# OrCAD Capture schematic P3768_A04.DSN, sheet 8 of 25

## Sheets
8 0017_DISPLAYPORT_HDMI: size Custom
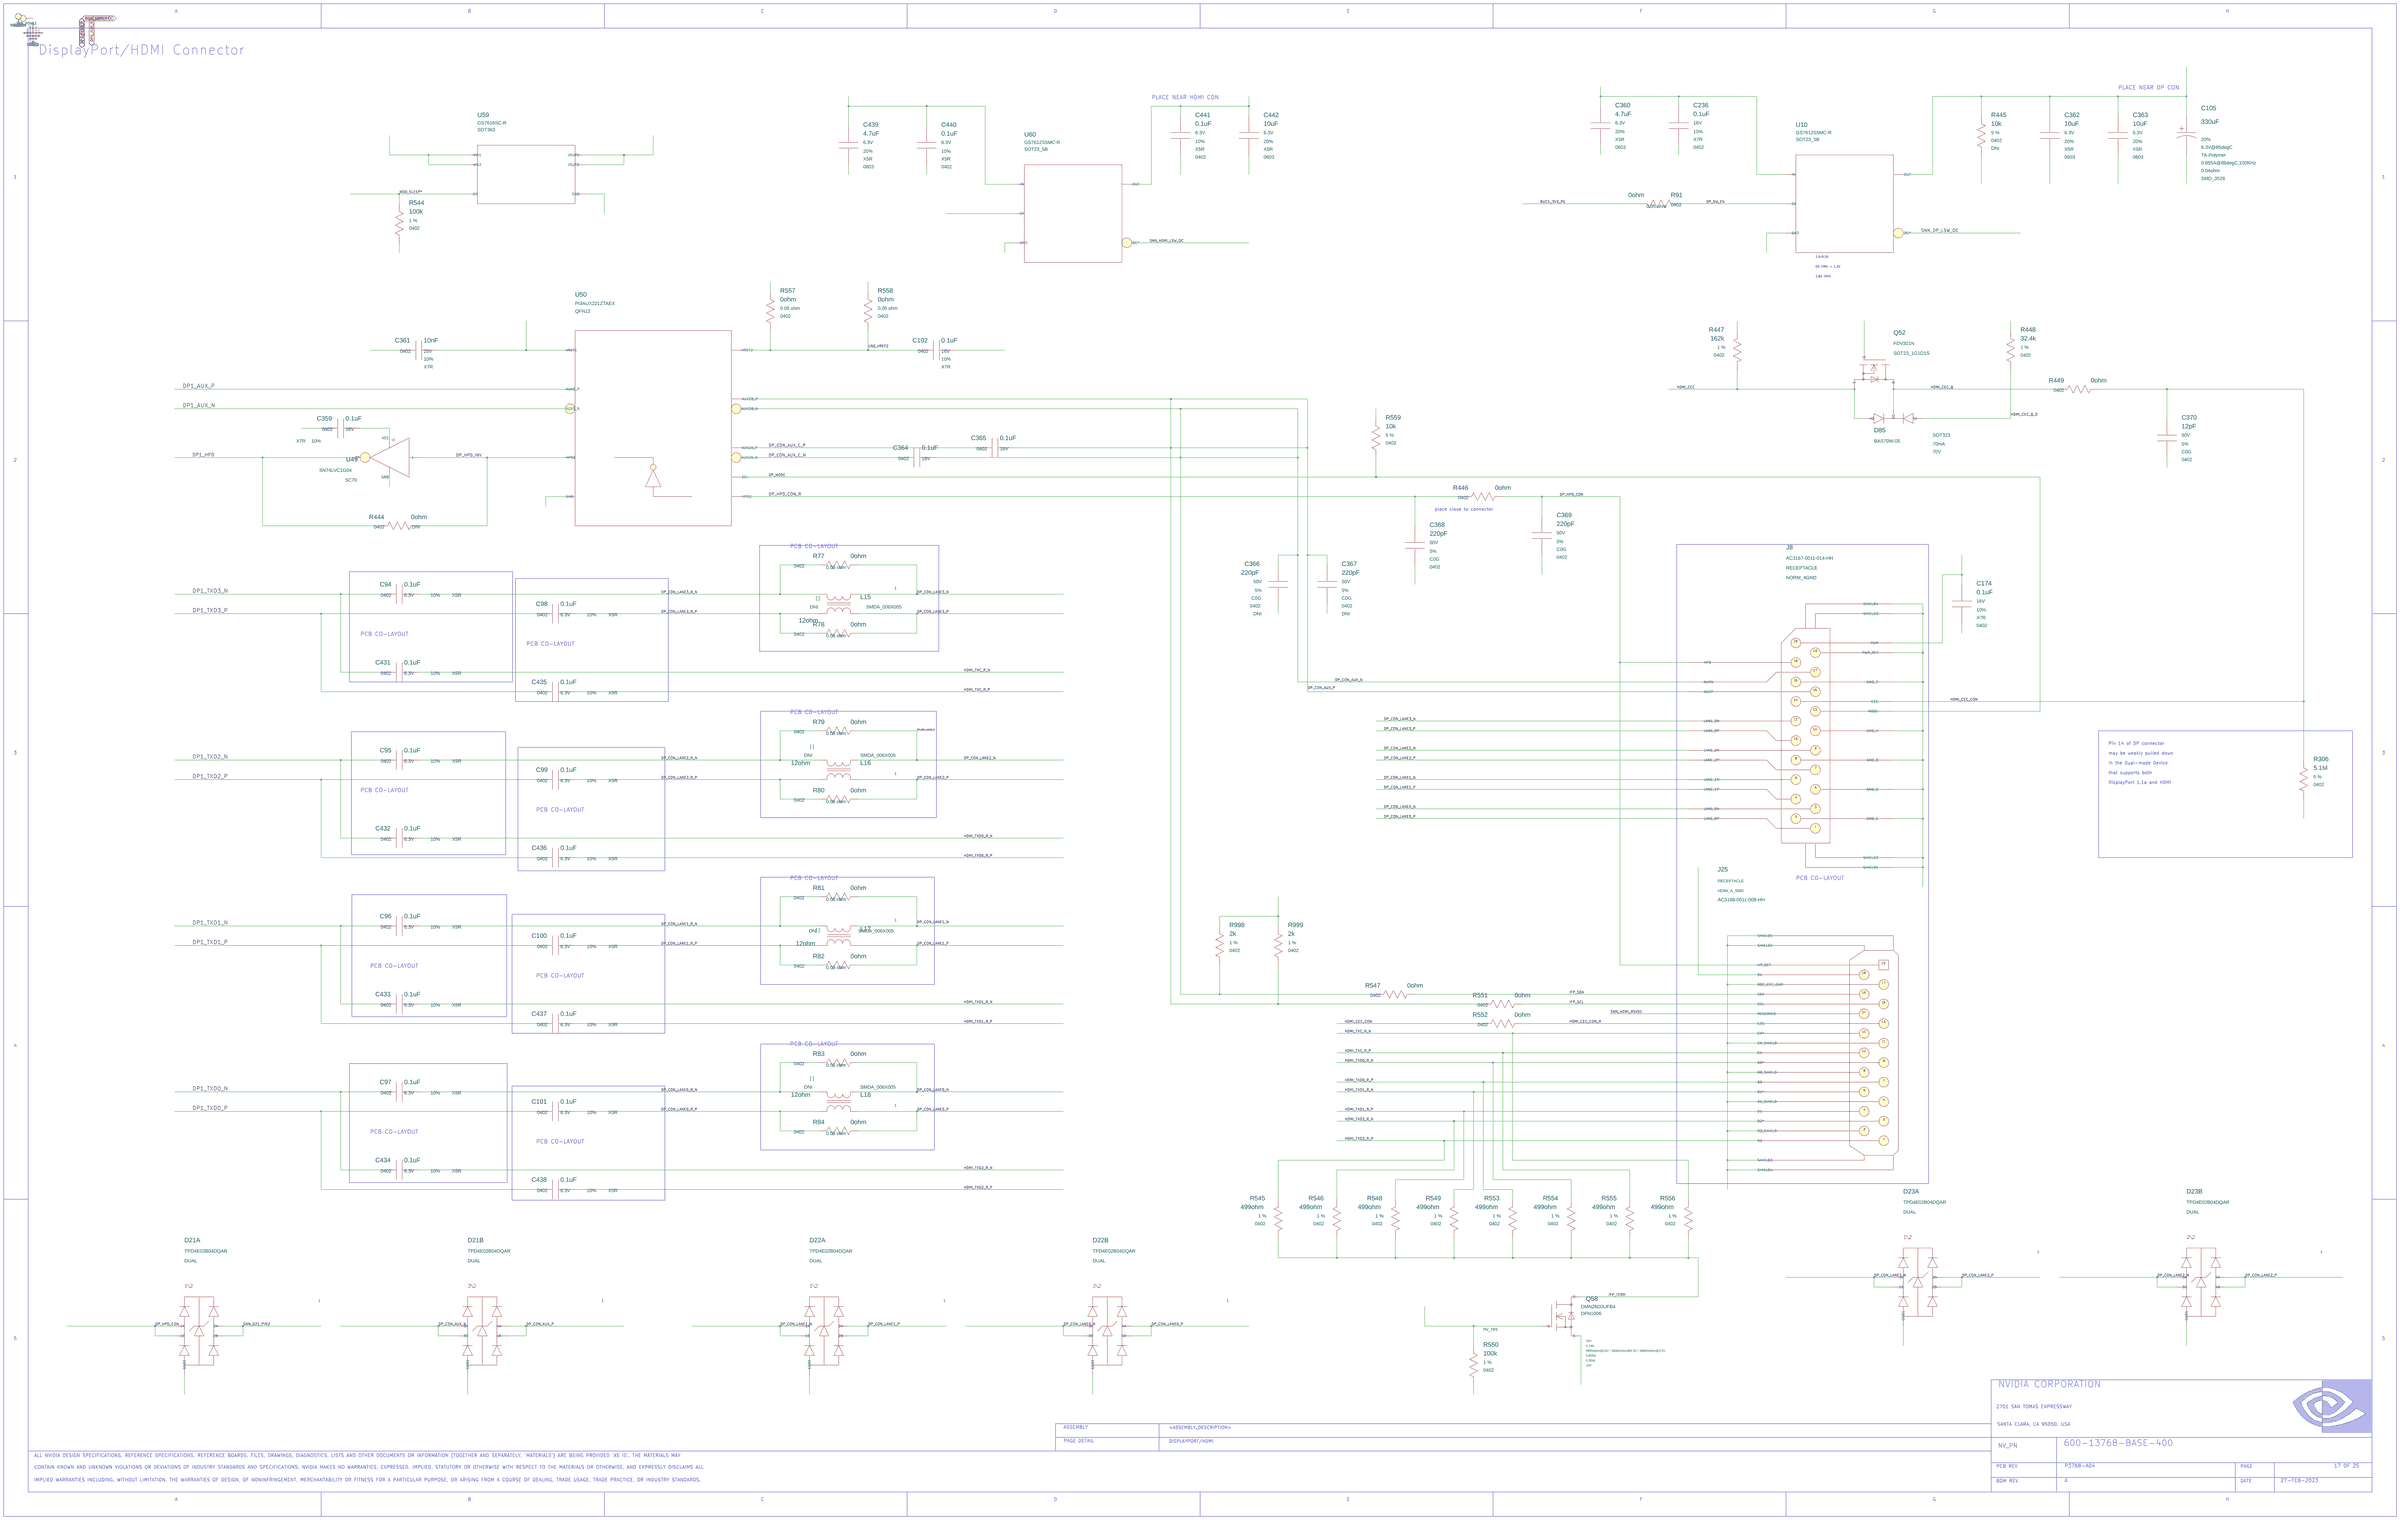
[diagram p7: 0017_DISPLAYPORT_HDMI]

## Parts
C94  0.1uF  [0402]
C95  0.1uF  [0402]
C96  0.1uF  [0402]
C97  0.1uF  [0402]
C98  0.1uF  [0402]
C99  0.1uF  [0402]
C100  0.1uF  [0402]
C101  0.1uF  [0402]
C102  0.1uF  [0402]
C105  330uF  [CAP_SMD_3528]
C174  0.1uF  [0402]
C236  0.1uF  [0402]
C359  0.1uF  [0402]
C360  4.7uF  [0603]
C361  10nF  [0402]
C362  10uF  [0603]
C363  10uF  [0603]
C364  0.1uF  [0402]
C365  0.1uF  [0402]
C366  220pF  [0402]
C367  220pF  [0402]
C368  220pF  [0402]
C369  220pF  [0402]
C370  12pF  [0402]
C431  0.1uF  [0402]
C432  0.1uF  [0402]
C433  0.1uF  [0402]
C434  0.1uF  [0402]
C435  0.1uF  [0402]
C436  0.1uF  [0402]
C437  0.1uF  [0402]
C438  0.1uF  [0402]
C439  4.7uF  [0603]
C440  0.1uF  [0402]
C441  0.1uF  [0402]
C442  10uF  [0603]
D21  D_ESD_DIFFPAIR  [TSLP10_P050_025X010]  (sections A,B)
D22  D_ESD_DIFFPAIR  [TSLP10_P050_025X010]  (sections A,B)
D23  D_ESD_DIFFPAIR  [TSLP10_P050_025X010]  (sections A,B)
D85  D_3PIN_CC  [SOT323]
J8  CON_DISPLAYPORT  [CON_DP_020_SMT_RA_F_P050]
J25  CON_HDMI  [CON_HDMI_019_SMT_RA_F_P005_R]
L15  12ohm  [FILTER_004_SMD_006X005]
L16  12ohm  [FILTER_004_SMD_006X005]
L17  12ohm  [FILTER_004_SMD_006X005]
L18  12ohm  [FILTER_004_SMD_006X005]
Q52  Q_FET_N_ENH  [SOT23]
Q58  Q_FET_N_ENH  [DFET_003_SMD_010X006_B]
R77  0ohm  [0402]
R78  0ohm  [0402]
R79  0ohm  [0402]
R80  0ohm  [0402]
R81  0ohm  [0402]
R82  0ohm  [0402]
R83  0ohm  [0402]
R84  0ohm  [0402]
R91  0ohm  [0402]
R306  5.1M  [0402]
R444  0ohm  [0402]
R445  10k  [0402]
R446  0ohm  [0402]
R447  162k  [0402]
R448  32.4k  [0402]
R449  0ohm  [0402]
R544  100k  [0402]
R545  499ohm  [0402]
R546  499ohm  [0402]
R547  0ohm  [0402]
R548  499ohm  [0402]
R549  499ohm  [0402]
R550  100k  [0402]
R551  0ohm  [0402]
R552  0ohm  [0402]
R553  499ohm  [0402]
R554  499ohm  [0402]
R555  499ohm  [0402]
R556  499ohm  [0402]
R557  0ohm  [0402]
R558  0ohm  [0402]
R559  10k  [0402]
R998  2k  [0402]
R999  2k  [0402]
U10  U_POWER_SW  [SOT23_5]
U49  U_NOT  [SC70_5]
U50  U_AUX_DDC_INTERFACE  [QFN012Q_P040_0020_B]
U59  U_SW_LOAD  [SC70_6]
U60  U_POWER_SW  [SOT23_5]

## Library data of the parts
C94 = C: ASSEMBLY: DISPLAYPORT; CDS_LIB: discrete; CDS_PART_NAME: C_0402-0.1UF,X5R,10%,6.3V,039-0007-000; CDS_PHYS_PART_NAME: C_0402-0.1UF,X5R,10%,6.3V,039-0007-000-0.1UF,039-0007-000; CDS_SEC: 1; DEVICE_TYPENAME: C_0402-01UFX5R1063V039-0007-000-01UF039-0007-000; DRAWING: @P3768_A04_LIB.P3768_A04(SCH_1):PAGE17; MAT: X5R; MAX_VOLTAGE: 6.3V; NO_XNET: 1; NV_PN: 039-0007-000; PATH: I276; PHYS_PAGE: 17; PSPICETEMPLATE: X^@REFDES  %1    %2   @NV_PN; ROT: 0; SEC: 1; SIGNAL_MODEL: nv_cap; TOL: 10%; VER: 2; XY: (-10100,4600)
C95 = C: ASSEMBLY: DISPLAYPORT; CDS_LIB: discrete; CDS_PART_NAME: C_0402-0.1UF,X5R,10%,6.3V,039-0007-000; CDS_PHYS_PART_NAME: C_0402-0.1UF,X5R,10%,6.3V,039-0007-000-0.1UF,039-0007-000; CDS_SEC: 1; DEVICE_TYPENAME: C_0402-01UFX5R1063V039-0007-000-01UF039-0007-000; DRAWING: @P3768_A04_LIB.P3768_A04(SCH_1):PAGE17; MAT: X5R; MAX_VOLTAGE: 6.3V; NO_XNET: 1; NV_PN: 039-0007-000; PATH: I273; PHYS_PAGE: 17; PSPICETEMPLATE: X^@REFDES  %1    %2   @NV_PN; ROT: 0; SEC: 1; SIGNAL_MODEL: nv_cap; TOL: 10%; VER: 2; XY: (-10100,3750)
C96 = C: ASSEMBLY: DISPLAYPORT; CDS_LIB: discrete; CDS_PART_NAME: C_0402-0.1UF,X5R,10%,6.3V,039-0007-000; CDS_PHYS_PART_NAME: C_0402-0.1UF,X5R,10%,6.3V,039-0007-000-0.1UF,039-0007-000; CDS_SEC: 1; DEVICE_TYPENAME: C_0402-01UFX5R1063V039-0007-000-01UF039-0007-000; DRAWING: @P3768_A04_LIB.P3768_A04(SCH_1):PAGE17; MAT: X5R; MAX_VOLTAGE: 6.3V; NO_XNET: 1; NV_PN: 039-0007-000; PATH: I272; PHYS_PAGE: 17; PSPICETEMPLATE: X^@REFDES  %1    %2   @NV_PN; ROT: 0; SEC: 1; SIGNAL_MODEL: nv_cap; TOL: 10%; VER: 2; XY: (-10100,2900)
C97 = C: ASSEMBLY: DISPLAYPORT; CDS_LIB: discrete; CDS_PART_NAME: C_0402-0.1UF,X5R,10%,6.3V,039-0007-000; CDS_PHYS_PART_NAME: C_0402-0.1UF,X5R,10%,6.3V,039-0007-000-0.1UF,039-0007-000; CDS_SEC: 1; DEVICE_TYPENAME: C_0402-01UFX5R1063V039-0007-000-01UF039-0007-000; DRAWING: @P3768_A04_LIB.P3768_A04(SCH_1):PAGE17; MAT: X5R; MAX_VOLTAGE: 6.3V; NO_XNET: 1; NV_PN: 039-0007-000; PATH: I271; PHYS_PAGE: 17; PSPICETEMPLATE: X^@REFDES  %1    %2   @NV_PN; ROT: 0; SEC: 1; SIGNAL_MODEL: nv_cap; TOL: 10%; VER: 2; XY: (-10100,2050)
C98 = C: ASSEMBLY: DISPLAYPORT; CDS_LIB: discrete; CDS_PART_NAME: C_0402-0.1UF,X5R,10%,6.3V,039-0007-000; CDS_PHYS_PART_NAME: C_0402-0.1UF,X5R,10%,6.3V,039-0007-000-0.1UF,039-0007-000; CDS_SEC: 1; DEVICE_TYPENAME: C_0402-01UFX5R1063V039-0007-000-01UF039-0007-000; DRAWING: @P3768_A04_LIB.P3768_A04(SCH_1):PAGE17; MAT: X5R; MAX_VOLTAGE: 6.3V; NO_XNET: 1; NV_PN: 039-0007-000; PATH: I288; PHYS_PAGE: 17; PSPICETEMPLATE: X^@REFDES  %1    %2   @NV_PN; ROT: 0; SEC: 1; SIGNAL_MODEL: nv_cap; TOL: 10%; VER: 2; XY: (-9300,4500)
C99 = C: ASSEMBLY: DISPLAYPORT; CDS_LIB: discrete; CDS_PART_NAME: C_0402-0.1UF,X5R,10%,6.3V,039-0007-000; CDS_PHYS_PART_NAME: C_0402-0.1UF,X5R,10%,6.3V,039-0007-000-0.1UF,039-0007-000; CDS_SEC: 1; DEVICE_TYPENAME: C_0402-01UFX5R1063V039-0007-000-01UF039-0007-000; DRAWING: @P3768_A04_LIB.P3768_A04(SCH_1):PAGE17; MAT: X5R; MAX_VOLTAGE: 6.3V; NO_XNET: 1; NV_PN: 039-0007-000; PATH: I279; PHYS_PAGE: 17; PSPICETEMPLATE: X^@REFDES  %1    %2   @NV_PN; ROT: 0; SEC: 1; SIGNAL_MODEL: nv_cap; TOL: 10%; VER: 2; XY: (-9300,3650)
C100 = C: ASSEMBLY: DISPLAYPORT; CDS_LIB: discrete; CDS_PART_NAME: C_0402-0.1UF,X5R,10%,6.3V,039-0007-000; CDS_PHYS_PART_NAME: C_0402-0.1UF,X5R,10%,6.3V,039-0007-000-0.1UF,039-0007-000; CDS_SEC: 1; DEVICE_TYPENAME: C_0402-01UFX5R1063V039-0007-000-01UF039-0007-000; DRAWING: @P3768_A04_LIB.P3768_A04(SCH_1):PAGE17; MAT: X5R; MAX_VOLTAGE: 6.3V; NO_XNET: 1; NV_PN: 039-0007-000; PATH: I278; PHYS_PAGE: 17; PSPICETEMPLATE: X^@REFDES  %1    %2   @NV_PN; ROT: 0; SEC: 1; SIGNAL_MODEL: nv_cap; TOL: 10%; VER: 2; XY: (-9300,2800)
C101 = C: ASSEMBLY: DISPLAYPORT; CDS_LIB: discrete; CDS_PART_NAME: C_0402-0.1UF,X5R,10%,6.3V,039-0007-000; CDS_PHYS_PART_NAME: C_0402-0.1UF,X5R,10%,6.3V,039-0007-000-0.1UF,039-0007-000; CDS_SEC: 1; DEVICE_TYPENAME: C_0402-01UFX5R1063V039-0007-000-01UF039-0007-000; DRAWING: @P3768_A04_LIB.P3768_A04(SCH_1):PAGE17; MAT: X5R; MAX_VOLTAGE: 6.3V; NO_XNET: 1; NV_PN: 039-0007-000; PATH: I277; PHYS_PAGE: 17; PSPICETEMPLATE: X^@REFDES  %1    %2   @NV_PN; ROT: 0; SEC: 1; SIGNAL_MODEL: nv_cap; TOL: 10%; VER: 2; XY: (-9300,1950)
C102 = C: ASSEMBLY: DP_AND_HDMI; CDS_LIB: discrete; CDS_PART_NAME: C_0402-0.1UF,X7R,10%,16V,032-0793-000; CDS_PHYS_PART_NAME: C_0402-0.1UF,X7R,10%,16V,032-0793-000-0.1UF,032-0793-000; CDS_SEC: 1; DEVICE_TYPENAME: C_0402-01UFX7R1016V032-0793-000-01UF032-0793-000; DRAWING: @P3768_A04_LIB.P3768_A04(SCH_1):PAGE17; MAT: X7R; MAX_VOLTAGE: 16V; NV_PN: 032-0793-000; PATH: I129; PHYS_PAGE: 17; PSPICETEMPLATE: X^@REFDES  %1    %2   @NV_PN; ROT: 0; SEC: 1; SIGNAL_MODEL: nv_cap; TOL: 10%; VER: 2; XY: (-7350,5850)
C105 = C_POL: ASSEMBLY: DISPLAYPORT; CDS_LIB: discrete; CDS_PART_NAME: C_POL_SMD_3528-330UF,TA-POLYMER,20%,6.3V@85DEGC,0.04OHM,9.999UH,0.855A@85DEGC,100KHZ,032-0696-000; CDS_PHYS_PART_NAME: C_POL_SMD_3528-330UF,TA-POLYMER,20%,6.3V@85DEGC,0.04OHM,9.999UH,0.855A@85DEGC,100KHZ,032-0696-000-032-0696-000,330UF; CDS_SEC: 1; DEVICE_TYPENAME: C_POL_SMD_3528-330UFTA-POLYMER2063V85DEGC004OHM9999UH0855A85DEGC100KHZ032-0696-000-032-0696-000330UF; DRAWING: @P3768_A04_LIB.P3768_A04(SCH_1):PAGE17; ESL: 9.999uH; ESR: 0.04ohm; MAT: TA-Polymer; MAX_VOLTAGE: 6.3V@85degC; NV_PN: 032-0696-000; PACK_TYPE: SMD_3528; PATH: I212; PHYS_PAGE: 17; PSPICETEMPLATE: X^@REFDES  %1    %2   @NV_PN; RIPPLE_CURRENT: 0.855A@85degC,100KHz; ROT: 0; SEC: 1; SIGNAL_MODEL: nv_capp; TOL: 20%; VER: 1; XY: (-950,6950)
C174 = C#1: ASSEMBLY: DISPLAYPORT; CDS_LIB: discrete; CDS_PART_NAME: C_0402-0.1UF,X7R,10%,16V,032-0793-000; CDS_PHYS_PART_NAME: C_0402-0.1UF,X7R,10%,16V,032-0793-000-0.1UF,032-0793-000; CDS_SEC: 1; CHIPS_PART_NAME: C; DEVICE_TYPENAME: C_0402-01UFX7R1016V032-0793-000-01UF032-0793-000; DRAWING: @P3768_A04_LIB.P3768_A04(SCH_1):PAGE17; MAT: X7R; MAX_VOLTAGE: 16V; NV_PN: 032-0793-000; PATH: I215; PHYS_PAGE: 17; PSPICETEMPLATE: X^@REFDES  %1    %2   @NV_PN; ROT: 0; SEC: 1; SIGNAL_MODEL: nv_cap; TOL: 10%; VER: 1; XY: (-2100,4550)
C236 = C#1: ASSEMBLY: DISPLAYPORT; CDS_LIB: discrete; CDS_PART_NAME: C_0402-0.1UF,X7R,10%,16V,032-0793-000; CDS_PHYS_PART_NAME: C_0402-0.1UF,X7R,10%,16V,032-0793-000-0.1UF,032-0793-000; CDS_SEC: 1; CHIPS_PART_NAME: C; DEVICE_TYPENAME: C_0402-01UFX7R1016V032-0793-000-01UF032-0793-000; DRAWING: @P3768_A04_LIB.P3768_A04(SCH_1):PAGE17; ESL: N/A; ESR: N/A; MAT: X7R; MAX_VOLTAGE: 16V; NV_PN: 032-0793-000; PATH: I197; PHYS_PAGE: 17; PSPICETEMPLATE: X^@REFDES  %1    %2   @NV_PN; ROT: 0; SEC: 1; SIGNAL_MODEL: nv_cap; TOL: 10%; VER: 1; XY: (-3550,7000)
C359 = C: ASSEMBLY: DP_AND_HDMI; CDS_LIB: discrete; CDS_PART_NAME: C_0402-0.1UF,X7R,10%,16V,032-0793-000; CDS_PHYS_PART_NAME: C_0402-0.1UF,X7R,10%,16V,032-0793-000-0.1UF,032-0793-000; CDS_SEC: 1; DEVICE_TYPENAME: C_0402-01UFX7R1016V032-0793-000-01UF032-0793-000; DRAWING: @P3768_A04_LIB.P3768_A04(SCH_1):PAGE17; MAT: X7R; MAX_VOLTAGE: 16V; NV_PN: 032-0793-000; PATH: I296; PHYS_PAGE: 17; ROT: 0; SEC: 1; SIGNAL_MODEL: nv_cap; TOL: 10%; VER: 2; XY: (-10400,5450)
C360 = C#1: ASSEMBLY: DISPLAYPORT; CDS_LIB: discrete; CDS_PART_NAME: C_0603-4.7UF,X5R,20%,6.3V,032-2124-000; CDS_PHYS_PART_NAME: C_0603-4.7UF,X5R,20%,6.3V,032-2124-000-032-2124-000,4.7UF; CDS_SEC: 1; CHIPS_PART_NAME: C; DEVICE_TYPENAME: C_0603-47UFX5R2063V032-2124-000-032-2124-00047UF; DRAWING: @P3768_A04_LIB.P3768_A04(SCH_1):PAGE17; MAT: X5R; MAX_VOLTAGE: 6.3V; NV_PN: 032-2124-000; PATH: I218; PHYS_PAGE: 17; PSPICETEMPLATE: X^@REFDES  %1    %2   @NV_PN; ROT: 0; SEC: 1; SIGNAL_MODEL: nv_cap; TOL: 20%; VER: 1; XY: (-3950,7000)
C361 = C: ASSEMBLY: DP_AND_HDMI; CDS_LIB: discrete; CDS_PART_NAME: C_0402-10NF,X7R,10%,25V,036-0019-000; CDS_PHYS_PART_NAME: C_0402-10NF,X7R,10%,25V,036-0019-000-036-0019-000,10NF; CDS_SEC: 1; DEVICE_TYPENAME: C_0402-10NFX7R1025V036-0019-000-036-0019-00010NF; DRAWING: @P3768_A04_LIB.P3768_A04(SCH_1):PAGE17; MAT: X7R; MAX_VOLTAGE: 25V; NV_PN: 036-0019-000; PATH: I176; PHYS_PAGE: 17; PSPICETEMPLATE: X^@REFDES  %1    %2   @NV_PN; ROT: 0; SEC: 1; SIGNAL_MODEL: nv_cap; TOL: 10%; VER: 2; XY: (-10000,5850)
C362 = C#1: ASSEMBLY: DISPLAYPORT; CDS_LIB: discrete; CDS_PART_NAME: C_0603-10UF,X5R,20%,6.3V,032-2136-000; CDS_PHYS_PART_NAME: C_0603-10UF,X5R,20%,6.3V,032-2136-000-032-2136-000,10UF; CDS_SEC: 1; CHIPS_PART_NAME: C; DEVICE_TYPENAME: C_0603-10UFX5R2063V032-2136-000-032-2136-00010UF; DRAWING: @P3768_A04_LIB.P3768_A04(SCH_1):PAGE17; MAT: X5R; MAX_VOLTAGE: 6.3V; NV_PN: 032-2136-000; PATH: I220; PHYS_PAGE: 17; PSPICETEMPLATE: X^@REFDES  %1    %2   @NV_PN; ROT: 0; SEC: 1; SIGNAL_MODEL: nv_cap; TOL: 20%; VER: 1; XY: (-1650,6950)
C363 = C#1: ASSEMBLY: DISPLAYPORT; CDS_LIB: discrete; CDS_PART_NAME: C_0603-10UF,X5R,20%,6.3V,032-2136-000; CDS_PHYS_PART_NAME: C_0603-10UF,X5R,20%,6.3V,032-2136-000-032-2136-000,10UF; CDS_SEC: 1; CHIPS_PART_NAME: C; DEVICE_TYPENAME: C_0603-10UFX5R2063V032-2136-000-032-2136-00010UF; DRAWING: @P3768_A04_LIB.P3768_A04(SCH_1):PAGE17; MAT: X5R; MAX_VOLTAGE: 6.3V; NV_PN: 032-2136-000; PATH: I219; PHYS_PAGE: 17; PSPICETEMPLATE: X^@REFDES  %1    %2   @NV_PN; ROT: 0; SEC: 1; SIGNAL_MODEL: nv_cap; TOL: 20%; VER: 1; XY: (-1300,6950)
C364 = C: ASSEMBLY: DP_AND_HDMI; CDS_LIB: discrete; CDS_PART_NAME: C_0402-0.1UF,X7R,10%,16V,032-0793-000; CDS_PHYS_PART_NAME: C_0402-0.1UF,X7R,10%,16V,032-0793-000-0.1UF,032-0793-000; CDS_SEC: 1; DEVICE_TYPENAME: C_0402-01UFX7R1016V032-0793-000-01UF032-0793-000; DRAWING: @P3768_A04_LIB.P3768_A04(SCH_1):PAGE17; MAT: X7R; MAX_VOLTAGE: 16V; NV_PN: 032-0793-000; PATH: I142; PHYS_PAGE: 17; PSPICETEMPLATE: X^@REFDES  %1    %2   @NV_PN; ROT: 0; SEC: 1; SIGNAL_MODEL: nv_cap; TOL: 10%; VER: 2; XY: (-7450,5300)
C365 = C: ASSEMBLY: DP_AND_HDMI; CDS_LIB: discrete; CDS_PART_NAME: C_0402-0.1UF,X7R,10%,16V,032-0793-000; CDS_PHYS_PART_NAME: C_0402-0.1UF,X7R,10%,16V,032-0793-000-0.1UF,032-0793-000; CDS_SEC: 1; DEVICE_TYPENAME: C_0402-01UFX7R1016V032-0793-000-01UF032-0793-000; DRAWING: @P3768_A04_LIB.P3768_A04(SCH_1):PAGE17; MAT: X7R; MAX_VOLTAGE: 16V; NV_PN: 032-0793-000; PATH: I141; PHYS_PAGE: 17; PSPICETEMPLATE: X^@REFDES  %1    %2   @NV_PN; ROT: 0; SEC: 1; SIGNAL_MODEL: nv_cap; TOL: 10%; VER: 2; XY: (-7050,5350)
C366 = C#1: ASSEMBLY: DISPLAYPORT; CDS_LIB: discrete; CDS_PART_NAME: C_0402-220PF,C0G,5%,50V,035-0024-000; CDS_PHYS_PART_NAME: C_0402-220PF,C0G,5%,50V,035-0024-000-035-0024-000,220PF; CDS_SEC: 1; CHIPS_PART_NAME: C; DEVICE_TYPENAME: C_0402-220PFC0G550V035-0024-000-035-0024-000220PF; DRAWING: @P3768_A04_LIB.P3768_A04(SCH_1):PAGE17; MAT: C0G; MAX_VOLTAGE: 50V; NV_PN: 035-0024-000; PATH: I143; PHYS_PAGE: 17; PSPICETEMPLATE: X^@REFDES  %1    %2   @NV_PN; ROT: 2; SEC: 1; SIGNAL_MODEL: nv_cap; SKU: DNI; TOL: 5%; VER: 1; XY: (-5600,4650)
C367 = C#1: ASSEMBLY: DISPLAYPORT; CDS_LIB: discrete; CDS_PART_NAME: C_0402-220PF,C0G,5%,50V,035-0024-000; CDS_PHYS_PART_NAME: C_0402-220PF,C0G,5%,50V,035-0024-000-035-0024-000,220PF; CDS_SEC: 1; CHIPS_PART_NAME: C; DEVICE_TYPENAME: C_0402-220PFC0G550V035-0024-000-035-0024-000220PF; DRAWING: @P3768_A04_LIB.P3768_A04(SCH_1):PAGE17; MAT: C0G; MAX_VOLTAGE: 50V; NV_PN: 035-0024-000; PATH: I144; PHYS_PAGE: 17; PSPICETEMPLATE: X^@REFDES  %1    %2   @NV_PN; ROT: 0; SEC: 1; SIGNAL_MODEL: nv_cap; SKU: DNI; TOL: 5%; VER: 1; XY: (-5350,4650)
C368 = C#1: ASSEMBLY: DP_AND_HDMI; CDS_LIB: discrete; CDS_PART_NAME: C_0402-220PF,C0G,5%,50V,035-0024-000; CDS_PHYS_PART_NAME: C_0402-220PF,C0G,5%,50V,035-0024-000-035-0024-000,220PF; CDS_SEC: 1; CHIPS_PART_NAME: C; DEVICE_TYPENAME: C_0402-220PFC0G550V035-0024-000-035-0024-000220PF; DRAWING: @P3768_A04_LIB.P3768_A04(SCH_1):PAGE17; MAT: C0G; MAX_VOLTAGE: 50V; NV_PN: 035-0024-000; PATH: I173; PHYS_PAGE: 17; PSPICETEMPLATE: X^@REFDES  %1    %2   @NV_PN; ROT: 0; SEC: 1; SIGNAL_MODEL: nv_cap; TOL: 5%; VER: 1; XY: (-4900,4850)
C369 = C#1: ASSEMBLY: DP_AND_HDMI; CDS_LIB: discrete; CDS_PART_NAME: C_0402-220PF,C0G,5%,50V,035-0024-000; CDS_PHYS_PART_NAME: C_0402-220PF,C0G,5%,50V,035-0024-000-035-0024-000,220PF; CDS_SEC: 1; CHIPS_PART_NAME: C; DEVICE_TYPENAME: C_0402-220PFC0G550V035-0024-000-035-0024-000220PF; DRAWING: @P3768_A04_LIB.P3768_A04(SCH_1):PAGE17; MAT: C0G; MAX_VOLTAGE: 50V; NV_PN: 035-0024-000; PATH: I172; PHYS_PAGE: 17; PSPICETEMPLATE: X^@REFDES  %1    %2   @NV_PN; ROT: 0; SEC: 1; SIGNAL_MODEL: nv_cap; TOL: 5%; VER: 1; XY: (-4250,4900)
C370 = C#1: ASSEMBLY: HDMI; CDS_LIB: discrete; CDS_PART_NAME: C_0402-12PF,C0G,5%,50V,035-0014-000; CDS_PHYS_PART_NAME: C_0402-12PF,C0G,5%,50V,035-0014-000-035-0014-000,12PF; CDS_SEC: 1; CHIPS_PART_NAME: C; DEVICE_TYPENAME: C_0402-12PFC0G550V035-0014-000-035-0014-00012PF; DRAWING: @P3768_A04_LIB.P3768_A04(SCH_1):PAGE17; ESL: N/A; ESR: N/A; MAT: C0G; MAX_VOLTAGE: 50V; NV_PN: 035-0014-000; PATH: I223; PHYS_PAGE: 17; PSPICETEMPLATE: X^@REFDES  %1    %2   @NV_PN; ROT: 0; SEC: 1; SIGNAL_MODEL: nv_cap; TOL: 5%; VER: 1; XY: (-1050,5400)
C431 = C: ASSEMBLY: HDMI; CDS_LIB: discrete; CDS_PART_NAME: C_0402-0.1UF,X5R,10%,6.3V,039-0007-000; CDS_PHYS_PART_NAME: C_0402-0.1UF,X5R,10%,6.3V,039-0007-000-0.1UF,039-0007-000; CDS_SEC: 1; DEVICE_TYPENAME: C_0402-01UFX5R1063V039-0007-000-01UF039-0007-000; DRAWING: @P3768_A04_LIB.P3768_A04(SCH_1):PAGE17; MAT: X5R; MAX_VOLTAGE: 6.3V; NO_XNET: 1; NV_PN: 039-0007-000; PATH: I301; PHYS_PAGE: 17; PSPICETEMPLATE: X^@REFDES  %1    %2   @NV_PN; ROT: 0; SEC: 1; SIGNAL_MODEL: nv_cap; TOL: 10%; VER: 2; XY: (-10100,4200)
C432 = C: ASSEMBLY: HDMI; CDS_LIB: discrete; CDS_PART_NAME: C_0402-0.1UF,X5R,10%,6.3V,039-0007-000; CDS_PHYS_PART_NAME: C_0402-0.1UF,X5R,10%,6.3V,039-0007-000-0.1UF,039-0007-000; CDS_SEC: 1; DEVICE_TYPENAME: C_0402-01UFX5R1063V039-0007-000-01UF039-0007-000; DRAWING: @P3768_A04_LIB.P3768_A04(SCH_1):PAGE17; MAT: X5R; MAX_VOLTAGE: 6.3V; NO_XNET: 1; NV_PN: 039-0007-000; PATH: I303; PHYS_PAGE: 17; PSPICETEMPLATE: X^@REFDES  %1    %2   @NV_PN; ROT: 0; SEC: 1; SIGNAL_MODEL: nv_cap; TOL: 10%; VER: 2; XY: (-10100,3350)
C433 = C: ASSEMBLY: HDMI; CDS_LIB: discrete; CDS_PART_NAME: C_0402-0.1UF,X5R,10%,6.3V,039-0007-000; CDS_PHYS_PART_NAME: C_0402-0.1UF,X5R,10%,6.3V,039-0007-000-0.1UF,039-0007-000; CDS_SEC: 1; DEVICE_TYPENAME: C_0402-01UFX5R1063V039-0007-000-01UF039-0007-000; DRAWING: @P3768_A04_LIB.P3768_A04(SCH_1):PAGE17; MAT: X5R; MAX_VOLTAGE: 6.3V; NO_XNET: 1; NV_PN: 039-0007-000; PATH: I305; PHYS_PAGE: 17; PSPICETEMPLATE: X^@REFDES  %1    %2   @NV_PN; ROT: 0; SEC: 1; SIGNAL_MODEL: nv_cap; TOL: 10%; VER: 2; XY: (-10100,2500)
C434 = C: ASSEMBLY: HDMI; CDS_LIB: discrete; CDS_PART_NAME: C_0402-0.1UF,X5R,10%,6.3V,039-0007-000; CDS_PHYS_PART_NAME: C_0402-0.1UF,X5R,10%,6.3V,039-0007-000-0.1UF,039-0007-000; CDS_SEC: 1; DEVICE_TYPENAME: C_0402-01UFX5R1063V039-0007-000-01UF039-0007-000; DRAWING: @P3768_A04_LIB.P3768_A04(SCH_1):PAGE17; MAT: X5R; MAX_VOLTAGE: 6.3V; NO_XNET: 1; NV_PN: 039-0007-000; PATH: I307; PHYS_PAGE: 17; PSPICETEMPLATE: X^@REFDES  %1    %2   @NV_PN; ROT: 0; SEC: 1; SIGNAL_MODEL: nv_cap; TOL: 10%; VER: 2; XY: (-10100,1650)
C435 = C: ASSEMBLY: HDMI; CDS_LIB: discrete; CDS_PART_NAME: C_0402-0.1UF,X5R,10%,6.3V,039-0007-000; CDS_PHYS_PART_NAME: C_0402-0.1UF,X5R,10%,6.3V,039-0007-000-0.1UF,039-0007-000; CDS_SEC: 1; DEVICE_TYPENAME: C_0402-01UFX5R1063V039-0007-000-01UF039-0007-000; DRAWING: @P3768_A04_LIB.P3768_A04(SCH_1):PAGE17; MAT: X5R; MAX_VOLTAGE: 6.3V; NO_XNET: 1; NV_PN: 039-0007-000; PATH: I302; PHYS_PAGE: 17; PSPICETEMPLATE: X^@REFDES  %1    %2   @NV_PN; ROT: 0; SEC: 1; SIGNAL_MODEL: nv_cap; TOL: 10%; VER: 2; XY: (-9300,4100)
C436 = C: ASSEMBLY: HDMI; CDS_LIB: discrete; CDS_PART_NAME: C_0402-0.1UF,X5R,10%,6.3V,039-0007-000; CDS_PHYS_PART_NAME: C_0402-0.1UF,X5R,10%,6.3V,039-0007-000-0.1UF,039-0007-000; CDS_SEC: 1; DEVICE_TYPENAME: C_0402-01UFX5R1063V039-0007-000-01UF039-0007-000; DRAWING: @P3768_A04_LIB.P3768_A04(SCH_1):PAGE17; MAT: X5R; MAX_VOLTAGE: 6.3V; NO_XNET: 1; NV_PN: 039-0007-000; PATH: I304; PHYS_PAGE: 17; PSPICETEMPLATE: X^@REFDES  %1    %2   @NV_PN; ROT: 0; SEC: 1; SIGNAL_MODEL: nv_cap; TOL: 10%; VER: 2; XY: (-9300,3250)
C437 = C: ASSEMBLY: HDMI; CDS_LIB: discrete; CDS_PART_NAME: C_0402-0.1UF,X5R,10%,6.3V,039-0007-000; CDS_PHYS_PART_NAME: C_0402-0.1UF,X5R,10%,6.3V,039-0007-000-0.1UF,039-0007-000; CDS_SEC: 1; DEVICE_TYPENAME: C_0402-01UFX5R1063V039-0007-000-01UF039-0007-000; DRAWING: @P3768_A04_LIB.P3768_A04(SCH_1):PAGE17; MAT: X5R; MAX_VOLTAGE: 6.3V; NO_XNET: 1; NV_PN: 039-0007-000; PATH: I306; PHYS_PAGE: 17; PSPICETEMPLATE: X^@REFDES  %1    %2   @NV_PN; ROT: 0; SEC: 1; SIGNAL_MODEL: nv_cap; TOL: 10%; VER: 2; XY: (-9300,2400)
C438 = C: ASSEMBLY: HDMI; CDS_LIB: discrete; CDS_PART_NAME: C_0402-0.1UF,X5R,10%,6.3V,039-0007-000; CDS_PHYS_PART_NAME: C_0402-0.1UF,X5R,10%,6.3V,039-0007-000-0.1UF,039-0007-000; CDS_SEC: 1; DEVICE_TYPENAME: C_0402-01UFX5R1063V039-0007-000-01UF039-0007-000; DRAWING: @P3768_A04_LIB.P3768_A04(SCH_1):PAGE17; MAT: X5R; MAX_VOLTAGE: 6.3V; NO_XNET: 1; NV_PN: 039-0007-000; PATH: I308; PHYS_PAGE: 17; PSPICETEMPLATE: X^@REFDES  %1    %2   @NV_PN; ROT: 0; SEC: 1; SIGNAL_MODEL: nv_cap; TOL: 10%; VER: 2; XY: (-9300,1550)
C439 = C#1: ASSEMBLY: HDMI; CDS_LIB: discrete; CDS_PART_NAME: C_0603-4.7UF,X5R,20%,6.3V,032-2124-000; CDS_PHYS_PART_NAME: C_0603-4.7UF,X5R,20%,6.3V,032-2124-000-032-2124-000,4.7UF; CDS_SEC: 1; CHIPS_PART_NAME: C; DEVICE_TYPENAME: C_0603-47UFX5R2063V032-2124-000-032-2124-00047UF; DRAWING: @P3768_A04_LIB.P3768_A04(SCH_1):PAGE17; MAT: X5R; MAX_VOLTAGE: 6.3V; NV_PN: 032-2124-000; PATH: I368; PHYS_PAGE: 17; ROT: 0; SEC: 1; SIGNAL_MODEL: nv_cap; TOL: 20%; VER: 1; XY: (-7800,6900)
C440 = C#1: ASSEMBLY: HDMI; CDS_LIB: discrete; CDS_PART_NAME: C_0402-0.1UF,X5R,10%,6.3V,039-0007-000; CDS_PHYS_PART_NAME: C_0402-0.1UF,X5R,10%,6.3V,039-0007-000-0.1UF,039-0007-000; CDS_SEC: 1; CHIPS_PART_NAME: C; DEVICE_TYPENAME: C_0402-01UFX5R1063V039-0007-000-01UF039-0007-000; DRAWING: @P3768_A04_LIB.P3768_A04(SCH_1):PAGE17; ESL: N/A; ESR: N/A; MAT: X5R; MAX_VOLTAGE: 6.3V; NV_PN: 039-0007-000; PATH: I366; PHYS_PAGE: 17; PSPICETEMPLATE: X^@REFDES  %1    %2   @NV_PN; ROT: 0; SEC: 1; SIGNAL_MODEL: nv_cap; TOL: 10%; VER: 1; XY: (-7400,6900)
C441 = C#1: ASSEMBLY: HDMI; CDS_LIB: discrete; CDS_PART_NAME: C_0402-0.1UF,X5R,10%,6.3V,039-0007-000; CDS_PHYS_PART_NAME: C_0402-0.1UF,X5R,10%,6.3V,039-0007-000-0.1UF,039-0007-000; CDS_SEC: 1; CHIPS_PART_NAME: C; DEVICE_TYPENAME: C_0402-01UFX5R1063V039-0007-000-01UF039-0007-000; DRAWING: @P3768_A04_LIB.P3768_A04(SCH_1):PAGE17; ESL: N/A; ESR: N/A; MAT: X5R; MAX_VOLTAGE: 6.3V; NV_PN: 039-0007-000; PATH: I364; PHYS_PAGE: 17; PSPICETEMPLATE: X^@REFDES  %1    %2   @NV_PN; ROT: 0; SEC: 1; SIGNAL_MODEL: nv_cap; TOL: 10%; VER: 1; XY: (-6100,6950)
C442 = C#1: ASSEMBLY: HDMI; CDS_LIB: discrete; CDS_PART_NAME: C_0603-10UF,X5R,20%,6.3V,032-2136-000; CDS_PHYS_PART_NAME: C_0603-10UF,X5R,20%,6.3V,032-2136-000-032-2136-000,10UF; CDS_SEC: 1; CHIPS_PART_NAME: C; DEVICE_TYPENAME: C_0603-10UFX5R2063V032-2136-000-032-2136-00010UF; DRAWING: @P3768_A04_LIB.P3768_A04(SCH_1):PAGE17; ESL: N/A; ESR: N/A; MAT: X5R; MAX_VOLTAGE: 6.3V; NV_PN: 032-2136-000; PATH: I365; PHYS_PAGE: 17; PSPICETEMPLATE: X^@REFDES  %1    %2   @NV_PN; ROT: 0; SEC: 1; SIGNAL_MODEL: nv_cap; TOL: 20%; VER: 1; XY: (-5750,6950)
D21 = D_ESD_DIFFPAIR: ASSEMBLY: DISPLAYPORT; BREAKDOWN_VOLTAGE_MIN_TYP: 6.7V; CAPACITANCE_MAX_TYP: 0.37pF; CDS_LIB: discrete; CDS_PART_NAME: D_ESD_DIFFPAIR_DUAL-TPD4E02B04DQAR,2 DIFFPAIR,BI-DIRECTIONAL,6V,0.01UA,6.7V,8V@40A,0.37PF,090-0296-000; CDS_PHYS_PART_NAME: D_ESD_DIFFPAIR_DUAL-TPD4E02B04DQAR,2 DIFFPAIR,BI-DIRECTIONAL,6V,0.01UA,6.7V,8V@40A,0.37PF,090-0296-000-090-0296-000; CDS_SEC: 2; CLAMPING_VOLTAGE: 8V@40A; CONFIGURATION: 2 Diffpair; CaptureCellPackProp: D_ESD_DIFFPAIRB; DEVICE_TYPENAME: D_ESD_DIFFPAIR_DUAL-TPD4E02B04DQAR2DIFFPAIRBI-DIRECTIONAL6V001UA67V8V40A037PF090-0296-000-090-0296-000; DRAWING: @P3768_A04_LIB.P3768_A04(SCH_1):PAGE17; MAX_REVERSE_LEAKAGE_CURRENT: 0.01uA; MAX_REVERSE_VOLTAGE: 6V; NO_XNET_CONNECTION: 1; NV_NAME: TPD4E02B04DQAR; NV_PN: 090-0296-000; PACK_TYPE: DUAL; PATH: I237; PHYS_PAGE: 17; POLARITY: Bi-Directional; ROT: 0; SEC: 2; VER: 2; XY: (-9700,850)
D22 = D_ESD_DIFFPAIR: ASSEMBLY: DISPLAYPORT; BREAKDOWN_VOLTAGE_MIN_TYP: 6.7V; CAPACITANCE_MAX_TYP: 0.37pF; CDS_LIB: discrete; CDS_PART_NAME: D_ESD_DIFFPAIR_DUAL-TPD4E02B04DQAR,2 DIFFPAIR,BI-DIRECTIONAL,6V,0.01UA,6.7V,8V@40A,0.37PF,090-0296-000; CDS_PHYS_PART_NAME: D_ESD_DIFFPAIR_DUAL-TPD4E02B04DQAR,2 DIFFPAIR,BI-DIRECTIONAL,6V,0.01UA,6.7V,8V@40A,0.37PF,090-0296-000-090-0296-000; CDS_SEC: 1; CLAMPING_VOLTAGE: 8V@40A; CONFIGURATION: 2 Diffpair; CaptureCellPackProp: D_ESD_DIFFPAIRA; DEVICE_TYPENAME: D_ESD_DIFFPAIR_DUAL-TPD4E02B04DQAR2DIFFPAIRBI-DIRECTIONAL6V001UA67V8V40A037PF090-0296-000-090-0296-000; DRAWING: @P3768_A04_LIB.P3768_A04(SCH_1):PAGE17; MAX_REVERSE_LEAKAGE_CURRENT: 0.01uA; MAX_REVERSE_VOLTAGE: 6V; NO_XNET_CONNECTION: 1; NV_NAME: TPD4E02B04DQAR; NV_PN: 090-0296-000; PACK_TYPE: DUAL; PATH: I238; PHYS_PAGE: 17; POLARITY: Bi-Directional; ROT: 0; SEC: 1; VER: 1; XY: (-7950,850)
D23 = D_ESD_DIFFPAIR: ASSEMBLY: DISPLAYPORT; BREAKDOWN_VOLTAGE_MIN_TYP: 6.7V; CAPACITANCE_MAX_TYP: 0.37pF; CDS_LIB: discrete; CDS_PART_NAME: D_ESD_DIFFPAIR_DUAL-TPD4E02B04DQAR,2 DIFFPAIR,BI-DIRECTIONAL,6V,0.01UA,6.7V,8V@40A,0.37PF,090-0296-000; CDS_PHYS_PART_NAME: D_ESD_DIFFPAIR_DUAL-TPD4E02B04DQAR,2 DIFFPAIR,BI-DIRECTIONAL,6V,0.01UA,6.7V,8V@40A,0.37PF,090-0296-000-090-0296-000; CDS_SEC: 1; CLAMPING_VOLTAGE: 8V@40A; CONFIGURATION: 2 Diffpair; CaptureCellPackProp: D_ESD_DIFFPAIRA; DEVICE_TYPENAME: D_ESD_DIFFPAIR_DUAL-TPD4E02B04DQAR2DIFFPAIRBI-DIRECTIONAL6V001UA67V8V40A037PF090-0296-000-090-0296-000; DRAWING: @P3768_A04_LIB.P3768_A04(SCH_1):PAGE17; MAX_REVERSE_LEAKAGE_CURRENT: 0.01uA; MAX_REVERSE_VOLTAGE: 6V; NO_XNET_CONNECTION: 1; NV_NAME: TPD4E02B04DQAR; NV_PN: 090-0296-000; PACK_TYPE: DUAL; PATH: I242; PHYS_PAGE: 17; POLARITY: Bi-Directional; ROT: 0; SEC: 1; VER: 1; XY: (-2350,1100)
D85 = D_3PIN_CC#1: ASSEMBLY: HDMI; CDS_LIB: discrete; CDS_PART_NAME: D_3PIN_CC_SOT323-BAS70W-05,1 PAIR - COMMON CATHODE,70V,0.1A,1V@15MA,70MA,091-0023-000; CDS_PHYS_PART_NAME: D_3PIN_CC_SOT323-BAS70W-05,1 PAIR - COMMON CATHODE,70V,0.1A,1V@15MA,70MA,091-0023-000-091-0023-000; CDS_SEC: 1; CONFIGURATION: 1 Pair - Common Cathode; CONTINUOUS_CURRENT: 70mA; DEVICE_TYPENAME: D_3PIN_CC_SOT323-BAS70W-051PAIR-COMMONCATHODE70V01A1V15MA70MA091-0023-000-091-0023-000; DRAWING: @P3768_A04_LIB.P3768_A04(SCH_1):PAGE17; FORWARD_VOLTAGE: 1V@15mA; MAX_CURRENT: 0.1A; MAX_VOLTAGE: 70V; NV_NAME: BAS70W-05; NV_PN: 091-0023-000; PATH: I229; PHYS_PAGE: 17; ROT: 6; SEC: 1; VER: 4; XY: (-2450,5500)
J8 = CON_DISPLAYPORT: ANGLE: 90; ASSEMBLY: DISPLAYPORT; CDS_LIB: electro_mechanic; CDS_PART_NAME: CON_DISPLAYPORT_NORM_4GND-AC3167-0011-014-HH,RECEPTACLE,0.5MM,90,YES,NO,NO,NO,YES,40 V,0.5 A,080-1898-000; CDS_PHYS_PART_NAME: CON_DISPLAYPORT_NORM_4GND-AC3167-0011-014-HH,RECEPTACLE,0.5MM,90,YES,NO,NO,NO,YES,40 V,0.5 A,080-1898-000-080-1898-000; CDS_SEC: 1; DEVICE_TYPENAME: CON_DISPLAYPORT_NORM_4GND-AC3167-0011-014-HHRECEPTACLE05MM90YESNONONOYES40V05A080-1898-000-080-1898-000; DRAWING: @P3768_A04_LIB.P3768_A04(SCH_1):PAGE17; EMI_GROUND_TAB: NO; GENDER: RECEPTACLE; LATCHING: NO; MAX_CURRENT: 0.5 A; MAX_VOLTAGE: 40 V; NV_NAME: AC3167-0011-014-HH; NV_PN: 080-1898-000; PACK_TYPE: NORM_4GND; PATH: I112; PHYS_PAGE: 17; PITCH: 0.5mm; REFLOW: YES; ROT: 0; SEC: 1; SHIELDED: YES; SHROUDED: NO; VER: 3; XY: (-2900,3850)
J25 = CON_HDMI: ANGLE: 90; ASSEMBLY: HDMI; CDS_LIB: electro_mechanic; CDS_PART_NAME: CON_HDMI_HDMI_A_SMD-AC3168-0011-008-HH,RECEPTACLE,0.5MM,90,YES,YES,NO,YES,YES,40 V,0.5 A,080-1838-000; CDS_PHYS_PART_NAME: CON_HDMI_HDMI_A_SMD-AC3168-0011-008-HH,RECEPTACLE,0.5MM,90,YES,YES,NO,YES,YES,40 V,0.5 A,080-1838-000-080-1838-000; CDS_SEC: 1; DEVICE_TYPENAME: CON_HDMI_HDMI_A_SMD-AC3168-0011-008-HHRECEPTACLE05MM90YESYESNOYESYES40V05A080-1838-000-080-1838-000; DRAWING: @P3768_A04_LIB.P3768_A04(SCH_1):PAGE17; EMI_GROUND_TAB: YES; GENDER: RECEPTACLE; LATCHING: NO; MAX_CURRENT: 0.5 A; MAX_VOLTAGE: 40 V; NV_NAME: AC3168-0011-008-HH; NV_PN: 080-1838-000; PACK_TYPE: HDMI_A_SMD; PATH: I300; PHYS_PAGE: 17; PITCH: 0.5mm; REFLOW: YES; ROT: 0; SEC: 1; SEC_TYPE: HDMI_A_SMD; SHIELDED: YES; SHROUDED: YES; SPARE: Astron; VER: 1; XY: (-2550,2250)
L15 = L_CMF_4P: ASSEMBLY: DISPLAYPORT; CDS_LIB: discrete; CDS_PART_NAME: L_CMF_4P_SMDA_006X005-12OHM,[ ],40%,0.1A,1OHM,TCM0605S-120-2P-T201,102-0051-000; CDS_PHYS_PART_NAME: L_CMF_4P_SMDA_006X005-12OHM,[ ],40%,0.1A,1OHM,TCM0605S-120-2P-T201,102-0051-000-102-0051-000,12OHM; CDS_SEC: 1; DC_RESISTANCE: 1ohm; DEVICE_TYPENAME: L_CMF_4P_SMDA_006X005-12OHM4001A1OHMTCM0605S-120-2P-T201102-0051-000-102-0051-00012OHM; DRAWING: @P3768_A04_LIB.P3768_A04(SCH_1):PAGE17; MAT: [ ]; MAX_CURRENT: 0.1A; NO_XNET_CONNECTION: 1; NV_NAME: TCM0605S-120-2P-T201; NV_PN: 102-0051-000; PACK_TYPE: SMDA_006X005; PATH: I289; PHYS_PAGE: 17; PLACEMENT_NOTE: CoLayout with R563, R565; ROT: 4; SEC: 1; SIGNAL_MODEL: nv_ind_cmf_4p; SKU: DNI; TOL: 40%; VER: 1; XY: (-7850,4550)
L16 = L_CMF_4P: ASSEMBLY: DISPLAYPORT; CDS_LIB: discrete; CDS_PART_NAME: L_CMF_4P_SMDA_006X005-12OHM,[ ],40%,0.1A,1OHM,TCM0605S-120-2P-T201,102-0051-000; CDS_PHYS_PART_NAME: L_CMF_4P_SMDA_006X005-12OHM,[ ],40%,0.1A,1OHM,TCM0605S-120-2P-T201,102-0051-000-102-0051-000,12OHM; CDS_SEC: 1; DC_RESISTANCE: 1ohm; DEVICE_TYPENAME: L_CMF_4P_SMDA_006X005-12OHM4001A1OHMTCM0605S-120-2P-T201102-0051-000-102-0051-00012OHM; DRAWING: @P3768_A04_LIB.P3768_A04(SCH_1):PAGE17; MAT: [ ]; MAX_CURRENT: 0.1A; NO_XNET_CONNECTION: 1; NV_NAME: TCM0605S-120-2P-T201; NV_PN: 102-0051-000; PACK_TYPE: SMDA_006X005; PATH: I284; PHYS_PAGE: 17; PLACEMENT_NOTE: CoLayout with R568, R571; ROT: 4; SEC: 1; SEC_TYPE: SMDA_006X005; SIGNAL_MODEL: nv_ind_cmf_4p; SKU: DNI; TOL: 40%; VER: 1; XY: (-7850,3700)
L17 = L_CMF_4P: ASSEMBLY: DISPLAYPORT; CDS_LIB: discrete; CDS_PART_NAME: L_CMF_4P_SMDA_006X005-12OHM,[ ],40%,0.1A,1OHM,TCM0605S-120-2P-T201,102-0051-000; CDS_PHYS_PART_NAME: L_CMF_4P_SMDA_006X005-12OHM,[ ],40%,0.1A,1OHM,TCM0605S-120-2P-T201,102-0051-000-102-0051-000,12OHM; CDS_SEC: 1; DC_RESISTANCE: 1ohm; DEVICE_TYPENAME: L_CMF_4P_SMDA_006X005-12OHM4001A1OHMTCM0605S-120-2P-T201102-0051-000-102-0051-00012OHM; DRAWING: @P3768_A04_LIB.P3768_A04(SCH_1):PAGE17; MAT: [ ]; MAX_CURRENT: 0.1A; NO_XNET_CONNECTION: 1; NV_NAME: TCM0605S-120-2P-T201; NV_PN: 102-0051-000; PACK_TYPE: SMDA_006X005; PATH: I282; PHYS_PAGE: 17; PLACEMENT_NOTE: CoLayout with R577, R579; ROT: 4; SEC: 1; SIGNAL_MODEL: nv_ind_cmf_4p; SKU: DNI; TOL: 40%; VER: 1; XY: (-7850,2850)
L18 = L_CMF_4P: ASSEMBLY: DISPLAYPORT; CDS_LIB: discrete; CDS_PART_NAME: L_CMF_4P_SMDA_006X005-12OHM,[ ],40%,0.1A,1OHM,TCM0605S-120-2P-T201,102-0051-000; CDS_PHYS_PART_NAME: L_CMF_4P_SMDA_006X005-12OHM,[ ],40%,0.1A,1OHM,TCM0605S-120-2P-T201,102-0051-000-102-0051-000,12OHM; CDS_SEC: 1; DC_RESISTANCE: 1ohm; DEVICE_TYPENAME: L_CMF_4P_SMDA_006X005-12OHM4001A1OHMTCM0605S-120-2P-T201102-0051-000-102-0051-00012OHM; DRAWING: @P3768_A04_LIB.P3768_A04(SCH_1):PAGE17; MAT: [ ]; MAX_CURRENT: 0.1A; NO_XNET_CONNECTION: 1; NV_NAME: TCM0605S-120-2P-T201; NV_PN: 102-0051-000; PACK_TYPE: SMDA_006X005; PATH: I291; PHYS_PAGE: 17; PLACEMENT_NOTE: CoLayout with R583, R584; ROT: 4; SEC: 1; SEC_TYPE: SMDA_006X005; SIGNAL_MODEL: nv_ind_cmf_4p; SKU: DNI; TOL: 40%; VER: 1; XY: (-7850,2000)
Q52 = Q_FET_N_ENH#1: ASSEMBLY: HDMI; CDS_LIB: discrete; CDS_PART_NAME: Q_FET_N_ENH_SOT23_1G1D1S-FDV301N,25V,-1000MOHM@10V / 4000MOHM@4.5V / -1000MOHM@2.5V,0.22A,0.5A,8V,0.35W,[ ]@10V / 0.7NC@4.5V / [ ]@2.5V,300-0494-000; CDS_PHYS_PART_NAME: Q_FET_N_ENH_SOT23_1G1D1S-FDV301N,25V,-1000MOHM@10V / 4000MOHM@4.5V / -1000MOHM@2.5V,0.22A,0.5A,8V,0.35W,[ ]@10V / 0.7NC@4.5V /B; CDS_SEC: 1; CONTINUOUS_CURRENT: 0.22A; CaptureCellPackProp: Q_FET_N_ENH##1; DEVICE_TYPENAME: Q_FET_N_ENH_SOT23_1G1D1S-FDV301N25V-1000MOHM10V4000MOHM45V-1000MOHM25V022A05A8V035W10V07NC45VB; DRAWING: @P3768_A04_LIB.P3768_A04(SCH_1):PAGE17; MAX_CURRENT: 0.5A; MAX_VOLTAGE: 25V; MAX_WATTAGE: 0.35W; NV_NAME: FDV301N; NV_PN: 300-0494-000; PACK_TYPE: SOT23_1G1D1S; PATH: I225; PHYS_PAGE: 17; Q_G: [ ]@10V / 0.7nC@4.5V / [ ]@2.5V; ROT: 5; R_DS_ON: -1000mohm@10V / 4000mohm@4.5V / -1000mohm@2.5V; SEC: 1; SYM4PACK_TYPE: 1G1D1S; VER: 2; V_BE_GS: 8V; XY: (-2550,5750)
Q58 = Q_FET_N_ENH#1: ASSEMBLY: HDMI; CDS_LIB: discrete; CDS_PART_NAME: Q_FET_N_ENH_DFN1006-DMN26D0UFB4,20V,999MOHM@10V / 3000MOHM@4.5V / 4000MOHM@2.5V,0.14A,0.805A,10V,0.35W,999NC@10V / 0NC@4.5V / 999NC@2.5V,300-0868-000; CDS_PHYS_PART_NAME: Q_FET_N_ENH_DFN1006-DMN26D0UFB4,20V,999MOHM@10V / 3000MOHM@4.5V / 4000MOHM@2.5V,0.14A,0.805A,10V,0.35W,999NC@10V / 0NC@4.5V / B; CDS_SEC: 1; CONTINUOUS_CURRENT: 0.14A; CaptureCellPackProp: Q_FET_N_ENH##1; DEVICE_TYPENAME: Q_FET_N_ENH_DFN1006-DMN26D0UFB420V999MOHM10V3000MOHM45V4000MOHM25V014A0805A10V035W999NC10V0NC45VB; DRAWING: @P3768_A04_LIB.P3768_A04(SCH_1):PAGE17; MAX_CURRENT: 0.805A; MAX_VOLTAGE: 20V; MAX_WATTAGE: 0.35W; NV_NAME: DMN26D0UFB4; NV_PN: 300-0868-000; PACK_TYPE: DFN1006; PATH: I331; PHYS_PAGE: 17; Q_G: 999nC@10V / 0nC@4.5V / 999nC@2.5V; ROT: 0; R_DS_ON: 999mohm@10V / 3000mohm@4.5V / 4000mohm@2.5V; SEC: 1; SYM4PACK_TYPE: 1G1D1S; VER: 2; V_BE_GS: 10V; XY: (-4150,900)
R77 = R#1: ASSEMBLY: DISPLAYPORT; CDS_LIB: discrete; CDS_PART_NAME: R_0402-0OHM,0.05 OHM,62.5MW,195-2655-000; CDS_PHYS_PART_NAME: R_0402-0OHM,0.05 OHM,62.5MW,195-2655-000-0OHM,195-2655-000; CDS_SEC: 1; CHIPS_PART_NAME: R; DEVICE_TYPENAME: R_0402-0OHM005OHM625MW195-2655-000-0OHM195-2655-000; DRAWING: @P3768_A04_LIB.P3768_A04(SCH_1):PAGE17; MAX_WATTAGE: 62.5mW; NV_PN: 195-2655-000; PATH: I290; PHYS_PAGE: 17; PLACEMENT_NOTE: CoLayout with L501; PSPICETEMPLATE: X^@REFDES  %1    %2   @NV_PN; ROT: 0; SEC: 1; SIGNAL_MODEL: nv_res; TOL: 0.05 ohm; VER: 1; XY: (-7850,4750)
R78 = R#1: ASSEMBLY: DISPLAYPORT; CDS_LIB: discrete; CDS_PART_NAME: R_0402-0OHM,0.05 OHM,62.5MW,195-2655-000; CDS_PHYS_PART_NAME: R_0402-0OHM,0.05 OHM,62.5MW,195-2655-000-0OHM,195-2655-000; CDS_SEC: 1; CHIPS_PART_NAME: R; DEVICE_TYPENAME: R_0402-0OHM005OHM625MW195-2655-000-0OHM195-2655-000; DRAWING: @P3768_A04_LIB.P3768_A04(SCH_1):PAGE17; MAX_WATTAGE: 62.5mW; NV_PN: 195-2655-000; PATH: I287; PHYS_PAGE: 17; PLACEMENT_NOTE: CoLayout with L501; PSPICETEMPLATE: X^@REFDES  %1    %2   @NV_PN; ROT: 0; SEC: 1; SIGNAL_MODEL: nv_res; TOL: 0.05 ohm; VER: 1; XY: (-7850,4400)
R79 = R#1: ASSEMBLY: DISPLAYPORT; CDS_LIB: discrete; CDS_PART_NAME: R_0402-0OHM,0.05 OHM,62.5MW,195-2655-000; CDS_PHYS_PART_NAME: R_0402-0OHM,0.05 OHM,62.5MW,195-2655-000-0OHM,195-2655-000; CDS_SEC: 1; CHIPS_PART_NAME: R; DEVICE_TYPENAME: R_0402-0OHM005OHM625MW195-2655-000-0OHM195-2655-000; DRAWING: @P3768_A04_LIB.P3768_A04(SCH_1):PAGE17; MAX_WATTAGE: 62.5mW; NV_PN: 195-2655-000; PATH: I286; PHYS_PAGE: 17; PLACEMENT_NOTE: CoLayout with L503; PSPICETEMPLATE: X^@REFDES  %1    %2   @NV_PN; ROT: 0; SEC: 1; SIGNAL_MODEL: nv_res; TOL: 0.05 ohm; VER: 1; XY: (-7850,3900)
R80 = R#1: ASSEMBLY: DISPLAYPORT; CDS_LIB: discrete; CDS_PART_NAME: R_0402-0OHM,0.05 OHM,62.5MW,195-2655-000; CDS_PHYS_PART_NAME: R_0402-0OHM,0.05 OHM,62.5MW,195-2655-000-0OHM,195-2655-000; CDS_SEC: 1; CHIPS_PART_NAME: R; DEVICE_TYPENAME: R_0402-0OHM005OHM625MW195-2655-000-0OHM195-2655-000; DRAWING: @P3768_A04_LIB.P3768_A04(SCH_1):PAGE17; MAX_WATTAGE: 62.5mW; NV_PN: 195-2655-000; PATH: I285; PHYS_PAGE: 17; PLACEMENT_NOTE: CoLayout with L503; PSPICETEMPLATE: X^@REFDES  %1    %2   @NV_PN; ROT: 0; SEC: 1; SIGNAL_MODEL: nv_res; TOL: 0.05 ohm; VER: 1; XY: (-7850,3550)
R81 = R#1: ASSEMBLY: DISPLAYPORT; CDS_LIB: discrete; CDS_PART_NAME: R_0402-0OHM,0.05 OHM,62.5MW,195-2655-000; CDS_PHYS_PART_NAME: R_0402-0OHM,0.05 OHM,62.5MW,195-2655-000-0OHM,195-2655-000; CDS_SEC: 1; CHIPS_PART_NAME: R; DEVICE_TYPENAME: R_0402-0OHM005OHM625MW195-2655-000-0OHM195-2655-000; DRAWING: @P3768_A04_LIB.P3768_A04(SCH_1):PAGE17; MAX_WATTAGE: 62.5mW; NV_PN: 195-2655-000; PATH: I283; PHYS_PAGE: 17; PLACEMENT_NOTE: CoLayout with L504; PSPICETEMPLATE: X^@REFDES  %1    %2   @NV_PN; ROT: 0; SEC: 1; SIGNAL_MODEL: nv_res; TOL: 0.05 ohm; VER: 1; XY: (-7850,3050)
R82 = R#1: ASSEMBLY: DISPLAYPORT; CDS_LIB: discrete; CDS_PART_NAME: R_0402-0OHM,0.05 OHM,62.5MW,195-2655-000; CDS_PHYS_PART_NAME: R_0402-0OHM,0.05 OHM,62.5MW,195-2655-000-0OHM,195-2655-000; CDS_SEC: 1; CHIPS_PART_NAME: R; DEVICE_TYPENAME: R_0402-0OHM005OHM625MW195-2655-000-0OHM195-2655-000; DRAWING: @P3768_A04_LIB.P3768_A04(SCH_1):PAGE17; MAX_WATTAGE: 62.5mW; NV_PN: 195-2655-000; PATH: I281; PHYS_PAGE: 17; PLACEMENT_NOTE: CoLayout with L504; PSPICETEMPLATE: X^@REFDES  %1    %2   @NV_PN; ROT: 0; SEC: 1; SIGNAL_MODEL: nv_res; TOL: 0.05 ohm; VER: 1; XY: (-7850,2700)
R83 = R#1: ASSEMBLY: DISPLAYPORT; CDS_LIB: discrete; CDS_PART_NAME: R_0402-0OHM,0.05 OHM,62.5MW,195-2655-000; CDS_PHYS_PART_NAME: R_0402-0OHM,0.05 OHM,62.5MW,195-2655-000-0OHM,195-2655-000; CDS_SEC: 1; CHIPS_PART_NAME: R; DEVICE_TYPENAME: R_0402-0OHM005OHM625MW195-2655-000-0OHM195-2655-000; DRAWING: @P3768_A04_LIB.P3768_A04(SCH_1):PAGE17; MAX_WATTAGE: 62.5mW; NV_PN: 195-2655-000; PATH: I280; PHYS_PAGE: 17; PLACEMENT_NOTE: CoLayout with L506; PSPICETEMPLATE: X^@REFDES  %1    %2   @NV_PN; ROT: 0; SEC: 1; SIGNAL_MODEL: nv_res; TOL: 0.05 ohm; VER: 1; XY: (-7850,2200)
R84 = R#1: ASSEMBLY: DISPLAYPORT; CDS_LIB: discrete; CDS_PART_NAME: R_0402-0OHM,0.05 OHM,62.5MW,195-2655-000; CDS_PHYS_PART_NAME: R_0402-0OHM,0.05 OHM,62.5MW,195-2655-000-0OHM,195-2655-000; CDS_SEC: 1; CHIPS_PART_NAME: R; DEVICE_TYPENAME: R_0402-0OHM005OHM625MW195-2655-000-0OHM195-2655-000; DRAWING: @P3768_A04_LIB.P3768_A04(SCH_1):PAGE17; MAX_WATTAGE: 62.5mW; NV_PN: 195-2655-000; PATH: I292; PHYS_PAGE: 17; PLACEMENT_NOTE: CoLayout with L506; PSPICETEMPLATE: X^@REFDES  %1    %2   @NV_PN; ROT: 0; SEC: 1; SIGNAL_MODEL: nv_res; TOL: 0.05 ohm; VER: 1; XY: (-7850,1850)
R91 = R#1: ASSEMBLY: DISPLAYPORT; CDS_LIB: discrete; CDS_PART_NAME: R_0402-0OHM,0.05 OHM,62.5MW,195-2655-000; CDS_PHYS_PART_NAME: R_0402-0OHM,0.05 OHM,62.5MW,195-2655-000-0OHM,195-2655-000; CDS_SEC: 1; CHIPS_PART_NAME: R; DEVICE_TYPENAME: R_0402-0OHM005OHM625MW195-2655-000-0OHM195-2655-000; DRAWING: @P3768_A04_LIB.P3768_A04(SCH_1):PAGE17; MAX_WATTAGE: 62.5mW; NV_PN: 195-2655-000; PATH: I221; PHYS_PAGE: 17; PSPICETEMPLATE: X^@REFDES  %1    %2   @NV_PN; ROT: 2; SEC: 1; SIGNAL_MODEL: nv_res; TOL: 0.05 ohm; VER: 1; XY: (-3650,6600)
R306 = R: ASSEMBLY: DISPLAYPORT; CDS_LIB: discrete; CDS_PART_NAME: R_0402-5.1M,5 %,62.5MW,195-0608-000; CDS_PHYS_PART_NAME: R_0402-5.1M,5 %,62.5MW,195-0608-000-195-0608-000,5.1M; CDS_SEC: 1; DEVICE_TYPENAME: R_0402-51M5625MW195-0608-000-195-0608-00051M; DRAWING: @P3768_A04_LIB.P3768_A04(SCH_1):PAGE17; MAX_WATTAGE: 62.5mW; NV_PN: 195-0608-000; PATH: I191; PHYS_PAGE: 17; PSPICETEMPLATE: X^@REFDES  %1    %2   @NV_PN; ROT: 0; SEC: 1; SIGNAL_MODEL: nv_res; TOL: 5 %; VER: 2; XY: (-350,3650)
R444 = R#1: ASSEMBLY: DP_AND_HDMI; CDS_LIB: discrete; CDS_PART_NAME: R_0402-0OHM,0.05 OHM,62.5MW,195-2655-000; CDS_PHYS_PART_NAME: R_0402-0OHM,0.05 OHM,62.5MW,195-2655-000-0OHM,195-2655-000; CDS_SEC: 1; CHIPS_PART_NAME: R; DEVICE_TYPENAME: R_0402-0OHM005OHM625MW195-2655-000-0OHM195-2655-000; DRAWING: @P3768_A04_LIB.P3768_A04(SCH_1):PAGE17; MAX_WATTAGE: 62.5mW; NV_PN: 195-2655-000; PATH: I178; PHYS_PAGE: 17; PSPICETEMPLATE: X^@REFDES  %1    %2   @NV_PN; ROT: 0; SEC: 1; SIGNAL_MODEL: nv_res; SKU: DNI; TOL: 0.05 ohm; VER: 1; XY: (-10100,4950)
R445 = R: ASSEMBLY: DISPLAYPORT; CDS_LIB: discrete; CDS_PART_NAME: R_0402-10K,5 %,62.5MW,195-0486-000; CDS_PHYS_PART_NAME: R_0402-10K,5 %,62.5MW,195-0486-000-10K,195-0486-000; CDS_SEC: 1; DEVICE_TYPENAME: R_0402-10K5625MW195-0486-000-10K195-0486-000; DRAWING: @P3768_A04_LIB.P3768_A04(SCH_1):PAGE17; MAX_WATTAGE: 62.5mW; NV_PN: 195-0486-000; PATH: I222; PHYS_PAGE: 17; ROT: 0; SEC: 1; SIGNAL_MODEL: nv_res; SKU: DNI; TOL: 5 %; VER: 2; XY: (-2000,6950)
R446 = R#1: ASSEMBLY: DP_AND_HDMI; CDS_LIB: discrete; CDS_PART_NAME: R_0402-0OHM,0.05 OHM,62.5MW,195-2655-000; CDS_PHYS_PART_NAME: R_0402-0OHM,0.05 OHM,62.5MW,195-2655-000-0OHM,195-2655-000; CDS_SEC: 1; CHIPS_PART_NAME: R; DEVICE_TYPENAME: R_0402-0OHM005OHM625MW195-2655-000-0OHM195-2655-000; DRAWING: @P3768_A04_LIB.P3768_A04(SCH_1):PAGE17; MAX_WATTAGE: 62.5mW; NV_PN: 195-2655-000; PATH: I171; PHYS_PAGE: 17; PSPICETEMPLATE: X^@REFDES  %1    %2   @NV_PN; ROT: 0; SEC: 1; SIGNAL_MODEL: nv_res; TOL: 0.05 ohm; VER: 1; XY: (-4550,5100)
R447 = R: ASSEMBLY: HDMI; CDS_LIB: discrete; CDS_PART_NAME: R_0402-162K,1 %,62.5MW,195-0106-000; CDS_PHYS_PART_NAME: R_0402-162K,1 %,62.5MW,195-0106-000-162K,195-0106-000; CDS_SEC: 1; DEVICE_TYPENAME: R_0402-162K1625MW195-0106-000-162K195-0106-000; DRAWING: @P3768_A04_LIB.P3768_A04(SCH_1):PAGE17; MAX_WATTAGE: 62.5mW; NV_PN: 195-0106-000; PATH: I232; PHYS_PAGE: 17; ROT: 2; SEC: 1; SIGNAL_MODEL: nv_res; TOL: 1 %; VER: 2; XY: (-3250,5850)
R448 = R: ASSEMBLY: HDMI; CDS_LIB: discrete; CDS_PART_NAME: R_0402-32.4K,1 %,62.5MW,195-0250-000; CDS_PHYS_PART_NAME: R_0402-32.4K,1 %,62.5MW,195-0250-000-195-0250-000,32.4K; CDS_SEC: 1; DEVICE_TYPENAME: R_0402-324K1625MW195-0250-000-195-0250-000324K; DRAWING: @P3768_A04_LIB.P3768_A04(SCH_1):PAGE17; MAX_WATTAGE: 62.5mW; NV_PN: 195-0250-000; PATH: I230; PHYS_PAGE: 17; ROT: 0; SEC: 1; SIGNAL_MODEL: nv_res; TOL: 1 %; VER: 2; XY: (-1850,5850)
R449 = R#1: ASSEMBLY: HDMI; CDS_LIB: discrete; CDS_PART_NAME: R_0402-0OHM,0.05 OHM,62.5MW,195-2655-000; CDS_PHYS_PART_NAME: R_0402-0OHM,0.05 OHM,62.5MW,195-2655-000-0OHM,195-2655-000; CDS_SEC: 1; CHIPS_PART_NAME: R; DEVICE_TYPENAME: R_0402-0OHM005OHM625MW195-2655-000-0OHM195-2655-000; DRAWING: @P3768_A04_LIB.P3768_A04(SCH_1):PAGE17; MAX_WATTAGE: 62.5mW; NV_PN: 195-2655-000; PATH: I224; PHYS_PAGE: 17; PLACEMENT_NOTE: CoLayout with L10; PSPICETEMPLATE: X^@REFDES  %1    %2   @NV_PN; ROT: 0; SEC: 1; SIGNAL_MODEL: DEFAULT_RESISTOR_0.001OHM_2_1; TOL: 0.05 ohm; VER: 1; XY: (-1500,5650)
R544 = R: ASSEMBLY: HDMI; CDS_LIB: discrete; CDS_PART_NAME: R_0402-100K,1 %,62.5MW,195-0005-000; CDS_PHYS_PART_NAME: R_0402-100K,1 %,62.5MW,195-0005-000-100K,195-0005-000; CDS_SEC: 1; DEVICE_TYPENAME: R_0402-100K1625MW195-0005-000-100K195-0005-000; DRAWING: @P3768_A04_LIB.P3768_A04(SCH_1):PAGE17; MAX_WATTAGE: 62.5mW; NV_PN: 195-0005-000; PATH: I357; PHYS_PAGE: 17; PSPICETEMPLATE: X^@REFDES  %1    %2   @NV_PN; ROT: 0; SEC: 1; SIGNAL_MODEL: nv_res; TOL: 1 %; VER: 2; XY: (-10100,6500)
R545 = R: ASSEMBLY: HDMI; CDS_LIB: discrete; CDS_PART_NAME: R_0402-499OHM,1 %,62.5MW,195-0338-000; CDS_PHYS_PART_NAME: R_0402-499OHM,1 %,62.5MW,195-0338-000-195-0338-000,499OHM; CDS_SEC: 1; DEVICE_TYPENAME: R_0402-499OHM1625MW195-0338-000-195-0338-000499OHM; DRAWING: @P3768_A04_LIB.P3768_A04(SCH_1):PAGE17; MAX_WATTAGE: 62.5mW; NO_XNET_CONNECTION: 1; NV_PN: 195-0338-000; PATH: I318; PHYS_PAGE: 17; ROT: 2; SEC: 1; SIGNAL_MODEL: nv_res; TOL: 1 %; VER: 2; XY: (-5600,1400)
R546 = R: ASSEMBLY: HDMI; CDS_LIB: discrete; CDS_PART_NAME: R_0402-499OHM,1 %,62.5MW,195-0338-000; CDS_PHYS_PART_NAME: R_0402-499OHM,1 %,62.5MW,195-0338-000-195-0338-000,499OHM; CDS_SEC: 1; DEVICE_TYPENAME: R_0402-499OHM1625MW195-0338-000-195-0338-000499OHM; DRAWING: @P3768_A04_LIB.P3768_A04(SCH_1):PAGE17; MAX_WATTAGE: 62.5mW; NO_XNET_CONNECTION: 1; NV_PN: 195-0338-000; PATH: I319; PHYS_PAGE: 17; ROT: 2; SEC: 1; SIGNAL_MODEL: nv_res; TOL: 1 %; VER: 2; XY: (-5300,1400)
R547 = R#1: ASSEMBLY: HDMI; CDS_LIB: discrete; CDS_PART_NAME: R_0402-0OHM,0.05 OHM,62.5MW,195-2655-000; CDS_PHYS_PART_NAME: R_0402-0OHM,0.05 OHM,62.5MW,195-2655-000-0OHM,195-2655-000; CDS_SEC: 1; CHIPS_PART_NAME: R; DEVICE_TYPENAME: R_0402-0OHM005OHM625MW195-2655-000-0OHM195-2655-000; DRAWING: @P3768_A04_LIB.P3768_A04(SCH_1):PAGE17; MAX_WATTAGE: 62.5mW; NV_PN: 195-2655-000; PATH: I360; PHYS_PAGE: 17; PSPICETEMPLATE: X^@REFDES  %1    %2   @NV_PN; ROT: 0; SEC: 1; SIGNAL_MODEL: nv_res; TOL: 0.05 ohm; VER: 1; XY: (-5000,2550)
R548 = R: ASSEMBLY: HDMI; CDS_LIB: discrete; CDS_PART_NAME: R_0402-499OHM,1 %,62.5MW,195-0338-000; CDS_PHYS_PART_NAME: R_0402-499OHM,1 %,62.5MW,195-0338-000-195-0338-000,499OHM; CDS_SEC: 1; DEVICE_TYPENAME: R_0402-499OHM1625MW195-0338-000-195-0338-000499OHM; DRAWING: @P3768_A04_LIB.P3768_A04(SCH_1):PAGE17; MAX_WATTAGE: 62.5mW; NO_XNET_CONNECTION: 1; NV_PN: 195-0338-000; PATH: I320; PHYS_PAGE: 17; ROT: 2; SEC: 1; SIGNAL_MODEL: nv_res; TOL: 1 %; VER: 2; XY: (-5000,1400)
R549 = R: ASSEMBLY: HDMI; CDS_LIB: discrete; CDS_PART_NAME: R_0402-499OHM,1 %,62.5MW,195-0338-000; CDS_PHYS_PART_NAME: R_0402-499OHM,1 %,62.5MW,195-0338-000-195-0338-000,499OHM; CDS_SEC: 1; DEVICE_TYPENAME: R_0402-499OHM1625MW195-0338-000-195-0338-000499OHM; DRAWING: @P3768_A04_LIB.P3768_A04(SCH_1):PAGE17; MAX_WATTAGE: 62.5mW; NO_XNET_CONNECTION: 1; NV_PN: 195-0338-000; PATH: I321; PHYS_PAGE: 17; ROT: 2; SEC: 1; SIGNAL_MODEL: nv_res; TOL: 1 %; VER: 2; XY: (-4700,1400)
R550 = R: ASSEMBLY: HDMI; CDS_LIB: discrete; CDS_PART_NAME: R_0402-100K,1 %,62.5MW,195-0005-000; CDS_PHYS_PART_NAME: R_0402-100K,1 %,62.5MW,195-0005-000-100K,195-0005-000; CDS_SEC: 1; DEVICE_TYPENAME: R_0402-100K1625MW195-0005-000-100K195-0005-000; DRAWING: @P3768_A04_LIB.P3768_A04(SCH_1):PAGE17; MAX_WATTAGE: 62.5mW; NV_PN: 195-0005-000; PATH: I332; PHYS_PAGE: 17; PSPICETEMPLATE: X^@REFDES  %1    %2   @NV_PN; ROT: 0; SEC: 1; SIGNAL_MODEL: nv_res; TOL: 1 %; VER: 2; XY: (-4600,650)
R551 = R#1: ASSEMBLY: HDMI; CDS_LIB: discrete; CDS_PART_NAME: R_0402-0OHM,0.05 OHM,62.5MW,195-2655-000; CDS_PHYS_PART_NAME: R_0402-0OHM,0.05 OHM,62.5MW,195-2655-000-0OHM,195-2655-000; CDS_SEC: 1; CHIPS_PART_NAME: R; DEVICE_TYPENAME: R_0402-0OHM005OHM625MW195-2655-000-0OHM195-2655-000; DRAWING: @P3768_A04_LIB.P3768_A04(SCH_1):PAGE17; MAX_WATTAGE: 62.5mW; NV_PN: 195-2655-000; PATH: I361; PHYS_PAGE: 17; PSPICETEMPLATE: X^@REFDES  %1    %2   @NV_PN; ROT: 0; SEC: 1; SIGNAL_MODEL: nv_res; TOL: 0.05 ohm; VER: 1; XY: (-4450,2500)
R552 = R#1: ASSEMBLY: HDMI; CDS_LIB: discrete; CDS_PART_NAME: R_0402-0OHM,0.05 OHM,62.5MW,195-2655-000; CDS_PHYS_PART_NAME: R_0402-0OHM,0.05 OHM,62.5MW,195-2655-000-0OHM,195-2655-000; CDS_SEC: 1; CHIPS_PART_NAME: R; DEVICE_TYPENAME: R_0402-0OHM005OHM625MW195-2655-000-0OHM195-2655-000; DRAWING: @P3768_A04_LIB.P3768_A04(SCH_1):PAGE17; MAX_WATTAGE: 62.5mW; NV_PN: 195-2655-000; PATH: I363; PHYS_PAGE: 17; PSPICETEMPLATE: X^@REFDES  %1    %2   @NV_PN; ROT: 0; SEC: 1; SIGNAL_MODEL: nv_res; TOL: 0.05 ohm; VER: 1; XY: (-4450,2400)
R553 = R: ASSEMBLY: HDMI; CDS_LIB: discrete; CDS_PART_NAME: R_0402-499OHM,1 %,62.5MW,195-0338-000; CDS_PHYS_PART_NAME: R_0402-499OHM,1 %,62.5MW,195-0338-000-195-0338-000,499OHM; CDS_SEC: 1; DEVICE_TYPENAME: R_0402-499OHM1625MW195-0338-000-195-0338-000499OHM; DRAWING: @P3768_A04_LIB.P3768_A04(SCH_1):PAGE17; MAX_WATTAGE: 62.5mW; NO_XNET_CONNECTION: 1; NV_PN: 195-0338-000; PATH: I322; PHYS_PAGE: 17; ROT: 2; SEC: 1; SIGNAL_MODEL: nv_res; TOL: 1 %; VER: 2; XY: (-4400,1400)
R554 = R: ASSEMBLY: HDMI; CDS_LIB: discrete; CDS_PART_NAME: R_0402-499OHM,1 %,62.5MW,195-0338-000; CDS_PHYS_PART_NAME: R_0402-499OHM,1 %,62.5MW,195-0338-000-195-0338-000,499OHM; CDS_SEC: 1; DEVICE_TYPENAME: R_0402-499OHM1625MW195-0338-000-195-0338-000499OHM; DRAWING: @P3768_A04_LIB.P3768_A04(SCH_1):PAGE17; MAX_WATTAGE: 62.5mW; NO_XNET_CONNECTION: 1; NV_PN: 195-0338-000; PATH: I323; PHYS_PAGE: 17; ROT: 2; SEC: 1; SIGNAL_MODEL: nv_res; TOL: 1 %; VER: 2; XY: (-4100,1400)
R555 = R: ASSEMBLY: HDMI; CDS_LIB: discrete; CDS_PART_NAME: R_0402-499OHM,1 %,62.5MW,195-0338-000; CDS_PHYS_PART_NAME: R_0402-499OHM,1 %,62.5MW,195-0338-000-195-0338-000,499OHM; CDS_SEC: 1; DEVICE_TYPENAME: R_0402-499OHM1625MW195-0338-000-195-0338-000499OHM; DRAWING: @P3768_A04_LIB.P3768_A04(SCH_1):PAGE17; MAX_WATTAGE: 62.5mW; NO_XNET_CONNECTION: 1; NV_PN: 195-0338-000; PATH: I324; PHYS_PAGE: 17; ROT: 2; SEC: 1; SIGNAL_MODEL: nv_res; TOL: 1 %; VER: 2; XY: (-3800,1400)
R556 = R: ASSEMBLY: HDMI; CDS_LIB: discrete; CDS_PART_NAME: R_0402-499OHM,1 %,62.5MW,195-0338-000; CDS_PHYS_PART_NAME: R_0402-499OHM,1 %,62.5MW,195-0338-000-195-0338-000,499OHM; CDS_SEC: 1; DEVICE_TYPENAME: R_0402-499OHM1625MW195-0338-000-195-0338-000499OHM; DRAWING: @P3768_A04_LIB.P3768_A04(SCH_1):PAGE17; MAX_WATTAGE: 62.5mW; NO_XNET_CONNECTION: 1; NV_PN: 195-0338-000; PATH: I325; PHYS_PAGE: 17; ROT: 2; SEC: 1; SIGNAL_MODEL: nv_res; TOL: 1 %; VER: 2; XY: (-3500,1400)
R557 = R: ASSEMBLY: DISPLAYPORT; CDS_LIB: discrete; CDS_PART_NAME: R_0402-0OHM,0.05 OHM,62.5MW,195-2655-000; CDS_PHYS_PART_NAME: R_0402-0OHM,0.05 OHM,62.5MW,195-2655-000-0OHM,195-2655-000; CDS_SEC: 1; DEVICE_TYPENAME: R_0402-0OHM005OHM625MW195-2655-000-0OHM195-2655-000; DRAWING: @P3768_A04_LIB.P3768_A04(SCH_1):PAGE17; MAX_WATTAGE: 62.5mW; NV_PN: 195-2655-000; PATH: I369; PHYS_PAGE: 17; ROT: 0; SEC: 1; SIGNAL_MODEL: nv_res; TOL: 0.05 ohm; VER: 2; XY: (-8200,6050)
R558 = R: ASSEMBLY: HDMI; CDS_LIB: discrete; CDS_PART_NAME: R_0402-0OHM,0.05 OHM,62.5MW,195-2655-000; CDS_PHYS_PART_NAME: R_0402-0OHM,0.05 OHM,62.5MW,195-2655-000-0OHM,195-2655-000; CDS_SEC: 1; DEVICE_TYPENAME: R_0402-0OHM005OHM625MW195-2655-000-0OHM195-2655-000; DRAWING: @P3768_A04_LIB.P3768_A04(SCH_1):PAGE17; MAX_WATTAGE: 62.5mW; NV_PN: 195-2655-000; PATH: I371; PHYS_PAGE: 17; ROT: 0; SEC: 1; SIGNAL_MODEL: nv_res; TOL: 0.05 ohm; VER: 2; XY: (-7700,6050)
R559 = R: ASSEMBLY: HDMI; CDS_LIB: discrete; CDS_PART_NAME: R_0402-10K,5 %,62.5MW,195-0486-000; CDS_PHYS_PART_NAME: R_0402-10K,5 %,62.5MW,195-0486-000-10K,195-0486-000; CDS_SEC: 1; DEVICE_TYPENAME: R_0402-10K5625MW195-0486-000-10K195-0486-000; DRAWING: @P3768_A04_LIB.P3768_A04(SCH_1):PAGE17; MAX_WATTAGE: 62.5mW; NV_PN: 195-0486-000; PATH: I374; PHYS_PAGE: 17; ROT: 0; SEC: 1; SIGNAL_MODEL: nv_res; TOL: 5 %; VER: 2; XY: (-5100,5400)
R998 = R: ASSEMBLY: HDMI; CDS_LIB: discrete; CDS_PART_NAME: R_0402-2K,1 %,62.5MW,195-0149-000; CDS_PHYS_PART_NAME: R_0402-2K,1 %,62.5MW,195-0149-000-195-0149-000,2K; CDS_SEC: 1; DEVICE_TYPENAME: R_0402-2K1625MW195-0149-000-195-0149-0002K; DRAWING: @P3768_A04_LIB.P3768_A04(SCH_1):PAGE17; MAX_WATTAGE: 62.5mW; NV_PN: 195-0149-000; PATH: I375; PHYS_PAGE: 17; ROT: 0; SEC: 1; TOL: 1 %; VER: 2; XY: (-5900,2800)
R999 = R: ASSEMBLY: HDMI; CDS_LIB: discrete; CDS_PART_NAME: R_0402-2K,1 %,62.5MW,195-0149-000; CDS_PHYS_PART_NAME: R_0402-2K,1 %,62.5MW,195-0149-000-195-0149-000,2K; CDS_SEC: 1; DEVICE_TYPENAME: R_0402-2K1625MW195-0149-000-195-0149-0002K; DRAWING: @P3768_A04_LIB.P3768_A04(SCH_1):PAGE17; MAX_WATTAGE: 62.5mW; NV_PN: 195-0149-000; PATH: I376; PHYS_PAGE: 17; ROT: 0; SEC: 1; TOL: 1 %; VER: 2; XY: (-5600,2800)
U10 = U_POWER_SW: ASSEMBLY: DISPLAYPORT; CDS_LIB: power_supply; CDS_PART_NAME: U_POWER_SW_SOT23_5B-GS7612S5MC-R,2V..5.5V,2V..5.5V,1.6A,SWITCH,315-0992-000; CDS_PHYS_PART_NAME: U_POWER_SW_SOT23_5B-GS7612S5MC-R,2V..5.5V,2V..5.5V,1.6A,SWITCH,315-0992-000-315-0992-000; CDS_SEC: 1; DEVICE_TYPENAME: U_POWER_SW_SOT23_5B-GS7612S5MC-R2V55V2V55V16ASWITCH315-0992-000-315-0992-000; DRAWING: @P3768_A04_LIB.P3768_A04(SCH_1):PAGE17; MAX_CURRENT: 1.6A; MAX_VOLTAGE: 2V..5.5V; NV_NAME: GS7612S5MC-R; NV_PN: 315-0992-000; OUTPUT_VOLTAGE: 2V..5.5V; PACK_TYPE: SOT23_5B; PATH: I298; PHYS_PAGE: 17; ROT: 0; SEC: 1; TYPE: Switch; VER: 7; XY: (-2700,6600)
U49 = U_NOT: ASSEMBLY: DP_AND_HDMI; CDS_LIB: logic; CDS_PART_NAME: U_NOT_SC70-SN74LVC1G04,GATES - NOT,115-0085-000; CDS_PHYS_PART_NAME: U_NOT_SC70-SN74LVC1G04,GATES - NOT,115-0085-000-115-0085-000; CDS_SEC: 1; DEVICE_TYPENAME: U_NOT_SC70-SN74LVC1G04GATES-NOT115-0085-000-115-0085-000; DRAWING: @P3768_A04_LIB.P3768_A04(SCH_1):PAGE17; FUNCTION: Gates - NOT; NV_NAME: SN74LVC1G04; NV_PN: 115-0085-000; PACK_TYPE: SC70; PATH: I177; PHYS_PAGE: 17; ROT: 2; SEC: 1; VER: 1; XY: (-10150,5300)
U50 = U_AUX_DDC_INTERFACE: ASSEMBLY: DP_AND_HDMI; CDS_LIB: digital; CDS_PART_NAME: U_AUX_DDC_INTERFACE_QFN12-PI3AUX221ZTAEX,OTHER,115-2838-000; CDS_PHYS_PART_NAME: U_AUX_DDC_INTERFACE_QFN12-PI3AUX221ZTAEX,OTHER,115-2838-000-115-2838-000; CDS_SEC: 1; DEVICE_TYPENAME: U_AUX_DDC_INTERFACE_QFN12-PI3AUX221ZTAEXOTHER115-2838-000-115-2838-000; DRAWING: @P3768_A04_LIB.P3768_A04(SCH_1):PAGE17; FUNCTION: Other; NV_NAME: PI3AUX221ZTAEX; NV_PN: 115-2838-000; PACK_TYPE: QFN12; PATH: I140; PHYS_PAGE: 17; ROT: 0; SEC: 1; VER: 1; XY: (-8800,5450)
